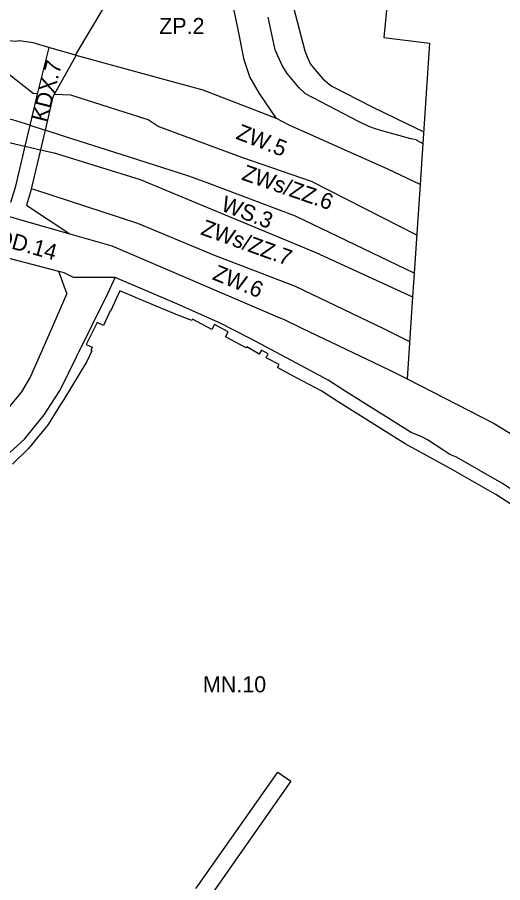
# Model space of a CAD drawing. Extents: x 7418991 to 7423142, y 5547704 to 5549547.
# Drawn here: x 7420312.9 to 7420464.2, y 5548281.5 to 5548551.2 of the extents above; entities that cross this region are included whole.
import ezdxf

# ---------------------------------------------------------------- set-up
doc = ezdxf.new("R2010")
doc.units = 0
for name, color, linetype in [('LIN_Linia Zabudowy Nieprzekraczalna', 7, 'Continuous'), ('LIN_linie_rozgraniczajace', 7, 'Continuous'), ('LIN_Orientacyjny przebieg terenow WS pod terenami komunikacyjnymi', 7, 'Continuous'), ('TXT_Oznaczenia_przeznaczen', 7, 'Continuous')]:
    doc.layers.add(name, color=color, linetype=linetype)

msp = doc.modelspace()

# ---------------------------------------------------------------- linework, layer by layer
at = {"layer": 'LIN_Linia Zabudowy Nieprzekraczalna'}
for points in [[(7420374.87, 5548615.32), (7420392.3, 5548595.58), (7420394.85, 5548578.9), (7420395.98, 5548571.46), (7420395.24, 5548571.14), (7420396.71, 5548567.74), (7420394.04, 5548566.59), (7420398.11, 5548557.14), (7420398.97, 5548554.26), (7420402.53, 5548540.72), (7420403.2, 5548538.9), (7420404.26, 5548536.65), (7420405.58, 5548534.97), (7420408.13, 5548532.08), (7420410.13, 5548530.34), (7420410.95, 5548529.8), (7420423.29, 5548523.41), (7420431.15, 5548519.58), (7420439.54, 5548515.56)], [(7420484.55, 5548387.96), (7420462.03, 5548402.46), (7420461.85, 5548402.56), (7420447.99, 5548410.51), (7420443.68, 5548412.85), (7420433.8, 5548418.27), (7420412.92, 5548431.33), (7420407.8, 5548434.65), (7420397.99, 5548439.9), (7420393.99, 5548442.03), (7420394.48, 5548442.95), (7420390.48, 5548445.1), (7420391.07, 5548446.3), (7420389.04, 5548447.42), (7420388.33, 5548446.25), (7420384.44, 5548448.46), (7420384.28, 5548448.16), (7420377.83, 5548451.62), (7420378.64, 5548453.15), (7420374.38, 5548455.44), (7420373.57, 5548453.91), (7420367.54, 5548457.16), (7420367.3, 5548456.7), (7420362.42, 5548458.61), (7420361.66, 5548458.91), (7420357.96, 5548460.48), (7420357.44, 5548460.69), (7420350.52, 5548463.6), (7420348.81, 5548464.29), (7420344.86, 5548465.93), (7420343.19, 5548462.3), (7420341.95, 5548459.66), (7420341.87, 5548459.7), (7420339.75, 5548455.19), (7420337.84, 5548456.13), (7420334.38, 5548449.26), (7420336.21, 5548448.42), (7420335.83, 5548447.4), (7420336.11, 5548447.27), (7420334.56, 5548443.97), (7420327.42, 5548432.12), (7420326.4, 5548430.5), (7420322.54, 5548424.28), (7420317.33, 5548417.98), (7420316.37, 5548416.85), (7420311.47, 5548411.98)]]:
    msp.add_lwpolyline(points, dxfattribs=at)
at = {"layer": 'LIN_linie_rozgraniczajace'}
for p, q in [((7420317.9, 5548527.42), (7420309.63, 5548533.94)), ((7420319.11, 5548527.37), (7420317.9, 5548527.42)), ((7420329.61, 5548526.91), (7420324.41, 5548527.14)), ((7420353.73, 5548519.3), (7420329.61, 5548526.91)), ((7420356.81, 5548517.18), (7420353.73, 5548519.3)), ((7420321.58, 5548516.02), (7420320.15, 5548509.94)), ((7420383.16, 5548507.37), (7420356.81, 5548517.18)), ((7420437.24, 5548513.06), (7420439.29, 5548511.83)), ((7420439.29, 5548511.83), (7420438.43, 5548499.09)), ((7420404.63, 5548499.99), (7420383.16, 5548507.37)), ((7420372.11, 5548499.57), (7420366.41, 5548501.67)), ((7420437.36, 5548483.28), (7420404.63, 5548499.99)), ((7420317.28, 5548497.73), (7420317.93, 5548497.61)), ((7420317.93, 5548497.61), (7420350.42, 5548487.03)), ((7420315.76, 5548492.7), (7420329.31, 5548483.73)), ((7420350.42, 5548487.03), (7420374.08, 5548477.19)), ((7420374.08, 5548477.19), (7420399.46, 5548467.42)), ((7420328.33, 5548465.17), (7420325.85, 5548472.03)), ((7420399.46, 5548467.42), (7420426.98, 5548454.22)), ((7420426.98, 5548454.22), (7420430.19, 5548452.7)), ((7420430.19, 5548452.7), (7420435.13, 5548450.15))]:
    msp.add_line(p, q, dxfattribs=at)
for points in [[(7420331.09, 5548539.41), (7420340.34, 5548554.86), (7420368.87, 5548589.02), (7420369.71, 5548589.74)], [(7420393.66, 5548519.63), (7420388.35, 5548527.46), (7420385.38, 5548532.68), (7420383.66, 5548537.98), (7420381.72, 5548547.38), (7420373.96, 5548584.35), (7420369.71, 5548589.74)], [(7420428.22, 5548556.56), (7420427.18, 5548544.91), (7420441.4, 5548543.17), (7420439.29, 5548511.83)], [(7420402.76, 5548527.37), (7420400.62, 5548529.37), (7420396.97, 5548533.7), (7420395.43, 5548536.15), (7420393.23, 5548541.07), (7420391.14, 5548551.21)], [(7420313.51, 5548543.89), (7420312.43, 5548543.71), (7420306.53, 5548544.23), (7420293.98, 5548546.02), (7420280.58, 5548547.3)], [(7420438.43, 5548499.09), (7420428.4, 5548503.84), (7420397.59, 5548517.57), (7420393.66, 5548519.63), (7420370.83, 5548528.54), (7420355.59, 5548532.7), (7420331.3, 5548539.35), (7420331.24, 5548539.37), (7420331.16, 5548539.39), (7420331.09, 5548539.41), (7420322.75, 5548541.8), (7420317.82, 5548543.21), (7420313.51, 5548543.89)], [(7420322.75, 5548541.8), (7420319.18, 5548527.65), (7420316.8, 5548517.55), (7420315.27, 5548511.05), (7420312.24, 5548498.16), (7420310.79, 5548493.54)], [(7420331.24, 5548539.37), (7420324.04, 5548526.47), (7420321.58, 5548516.02)], [(7420424.21, 5548516.56), (7420422.49, 5548517.22), (7420419.22, 5548518.76), (7420402.76, 5548527.37)], [(7420316.8, 5548517.55), (7420311.39, 5548519.28), (7420292.38, 5548522.88), (7420272.31, 5548523.1), (7420239.8, 5548525.23), (7420208.56, 5548523.24), (7420181.75, 5548524.11), (7420151.53, 5548524.46), (7420150.72, 5548524.39)], [(7420180.36, 5548517.54), (7420203.18, 5548518.38), (7420223.79, 5548515.78), (7420230.78, 5548517.2), (7420243.46, 5548518.36), (7420252.36, 5548518.3), (7420292.72, 5548514.97), (7420307.65, 5548512.78), (7420315.27, 5548511.05)], [(7420366.41, 5548501.67), (7420347.86, 5548507.58), (7420327.65, 5548514.07), (7420321.58, 5548516.02)], [(7420437.24, 5548513.06), (7420435.58, 5548513.32), (7420426.22, 5548515.93), (7420424.21, 5548516.56)], [(7420320.15, 5548509.94), (7420317.07, 5548496.84), (7420315.76, 5548492.7)], [(7420320.15, 5548509.94), (7420324.37, 5548508.98), (7420351.16, 5548500.62)], [(7420351.16, 5548500.62), (7420378.89, 5548489.16), (7420405.91, 5548477.94), (7420436.07, 5548464.08)], [(7420436.57, 5548471.43), (7420428.84, 5548475.18), (7420399.56, 5548489.25), (7420372.11, 5548499.57)], [(7420438.43, 5548499.09), (7420436.57, 5548471.43), (7420436.07, 5548464.08), (7420434.35, 5548438.55), (7420461.53, 5548424.61), (7420477.91, 5548414.57), (7420492.78, 5548405.41), (7420519.26, 5548389.1), (7420548.5, 5548366.71), (7420560.25, 5548358.05), (7420568.7, 5548351.61), (7420580.26, 5548342.08), (7420597.79, 5548325.09), (7420604.35, 5548319.1), (7420606.03, 5548317.56), (7420609.48, 5548313.8), (7420611.83, 5548311.24), (7420632.33, 5548284.25), (7420680.09, 5548200.38), (7420703.55, 5548157.78)], [(7420282.26, 5548493.03), (7420298.88, 5548492.32), (7420307.66, 5548489.91), (7420309.48, 5548489.39), (7420314.29, 5548488.01)], [(7420314.29, 5548488.01), (7420329.31, 5548483.73), (7420342.39, 5548479.99), (7420343.58, 5548479.42)], [(7420330.47, 5548470.16), (7420327.57, 5548471.58), (7420325.85, 5548472.03), (7420296.52, 5548479.65), (7420283.8, 5548481.93), (7420271.25, 5548482.64), (7420261.45, 5548480.64), (7420254.99, 5548474.39), (7420242.67, 5548462.51)], [(7420343.58, 5548479.42), (7420394.73, 5548457.59), (7420395.87, 5548457.08), (7420401.61, 5548454.32), (7420428.84, 5548441.38), (7420434.35, 5548438.55)], [(7420191.37, 5548290.16), (7420192.24, 5548292.52), (7420217.89, 5548319.42), (7420242.02, 5548343.53), (7420304.85, 5548409.98), (7420306.38, 5548411.15), (7420308.4, 5548413.59), (7420315.16, 5548419.76), (7420321.32, 5548427.36), (7420324.56, 5548432.31), (7420326.3, 5548434.96), (7420331.4, 5548445.41), (7420341.19, 5548465.32), (7420343.42, 5548470.14)], [(7420464.16, 5548405.84), (7420463.88, 5548406.01), (7420449.79, 5548414.09), (7420447.74, 5548414.99), (7420445.84, 5548416.21), (7420440.7, 5548419.52), (7420438.99, 5548420.41), (7420435.66, 5548421.83), (7420415.07, 5548434.71), (7420409.83, 5548438.1), (7420399.87, 5548443.43), (7420385.74, 5548450.95), (7420375.89, 5548456.01), (7420362.65, 5548461.9), (7420343.42, 5548470.14), (7420330.47, 5548470.16)], [(7420328.33, 5548465.17), (7420322.86, 5548452.47), (7420317.05, 5548439.23), (7420314.25, 5548434.48), (7420307.45, 5548426.37), (7420280.85, 5548450.7), (7420279.61, 5548449.42), (7420268.58, 5548436.74), (7420242.67, 5548462.51)], [(7420482.08, 5548394.21), (7420479.32, 5548395.93), (7420464.16, 5548405.84)], [(7420368.53, 5548279.65), (7420369.13, 5548280.52), (7420394.07, 5548315.91), (7420398.15, 5548313.14), (7420383.79, 5548292.65), (7420373.91, 5548278.55), (7420373.93, 5548277.94)]]:
    msp.add_lwpolyline(points, dxfattribs=at)
at = {"layer": 'LIN_Orientacyjny przebieg terenow WS pod terenami komunikacyjnymi'}
for p, q in [((7420316.8, 5548517.55), (7420321.62, 5548515.99)), ((7420315.27, 5548511.05), (7420320.15, 5548509.94))]:
    msp.add_line(p, q, dxfattribs=at)

# ---------------------------------------------------------------- texts
at = {"layer": 'TXT_Oznaczenia_przeznaczen'}
for s, p in [('ZP.2', (7420357.13, 5548546.01)), ('MN.10', (7420370.77, 5548340.81))]:
    msp.add_text(s, height=5, dxfattribs=at).set_placement(p)
for s, rotation, p in [('KDX.7', 75.7237, (7420322.14, 5548518.25)), ('ZW.5', 338.8091, (7420380.77, 5548513.44)), ('ZWs/ZZ.6', 340.8424, (7420382.54, 5548500.68)), ('WS.3', 339.0078, (7420376.06, 5548491.07)), ('KDD.14', 344.6018, (7420301.88, 5548481.63)), ('ZWs/ZZ.7', 340.2287, (7420369.77, 5548483.6)), ('ZW.6', 337.9584, (7420373.42, 5548469.62))]:
    msp.add_text(s, height=5, rotation=rotation, dxfattribs=at).set_placement(p)

doc.saveas('drawing.dxf')
